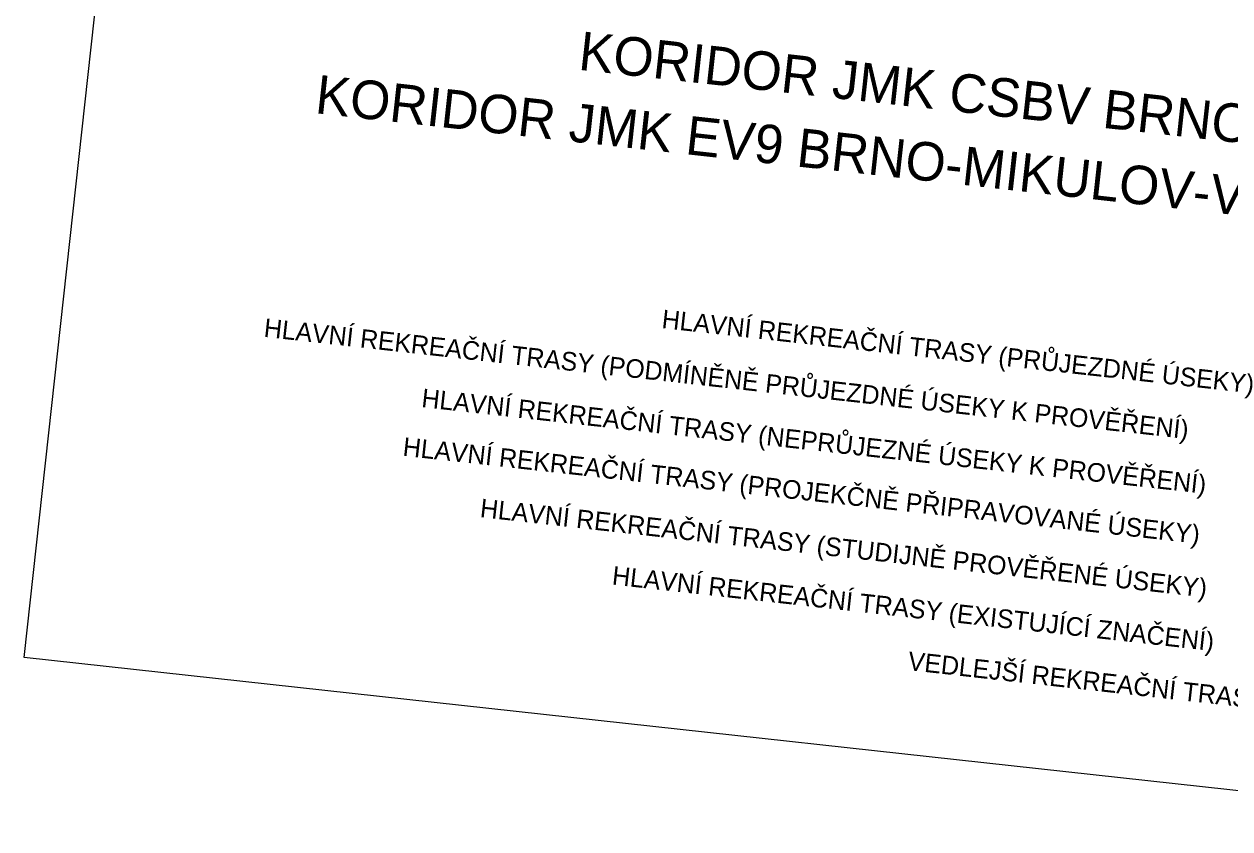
# Model space of a CAD drawing. Extents: x -678204 to -526855, y -1228851 to -1110393.
# Drawn here: x -626233 to -610673, y -1222167 to -1211785 of the extents above; entities that cross this region are included whole.
import ezdxf

# ---------------------------------------------------------------- set-up
doc = ezdxf.new("R2010")
doc.units = 0
for name, color, linetype in [('00_n_legenda popisy', 7, 'Continuous'), ('00_n_legenda popisy_hlavni', 7, 'Continuous'), ('_HELP BIG', 7, 'Continuous')]:
    doc.layers.add(name, color=color, linetype=linetype)

msp = doc.modelspace()

# ---------------------------------------------------------------- linework, layer by layer
at = {"layer": '_HELP BIG'}
msp.add_lwpolyline([(-626233, -1219955), (-623127, -1191667), (-602982, -1193879), (-606088, -1222167)], close=True, dxfattribs=at)

# ---------------------------------------------------------------- texts
at = {"layer": '00_n_legenda popisy'}
for s, p in [('HLAVNÍ REKREAČNÍ TRASY (PRŮJEZDNÉ ÚSEKY) ', (-618013, -1215705)), ('HLAVNÍ REKREAČNÍ TRASY (PODMÍNĚNĚ PRŮJEZDNÉ ÚSEKY K PROVĚŘENÍ) ', (-623148, -1215818)), ('HLAVNÍ REKREAČNÍ TRASY (NEPRŮJEZNÉ ÚSEKY K PROVĚŘENÍ) ', (-621113, -1216724)), ('HLAVNÍ REKREAČNÍ TRASY (PROJEKČNĚ PŘIPRAVOVANÉ ÚSEKY) ', (-621355, -1217352)), ('HLAVNÍ REKREAČNÍ TRASY (STUDIJNĚ PROVĚŘENÉ ÚSEKY) ', (-620358, -1218144)), ('HLAVNÍ REKREAČNÍ TRASY (EXISTUJÍCÍ ZNAČENÍ) ', (-618654, -1219014)), ('VEDLEJŠÍ REKREAČNÍ TRASY ', (-614837, -1220117))]:
    msp.add_text(s, height=240, rotation=353.6836, dxfattribs=at).set_placement(p)
at = {"layer": '00_n_legenda popisy_hlavni'}
for s, p in [('KORIDOR JMK CSBV BRNO-VÍDEŇ', (-619092, -1212372)), ('KORIDOR JMK EV9 BRNO-MIKULOV-VÍDEŇ', (-622490, -1212932))]:
    msp.add_text(s, height=497.66, rotation=353.6836, dxfattribs=at).set_placement(p)

doc.saveas('drawing.dxf')
